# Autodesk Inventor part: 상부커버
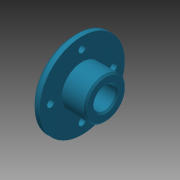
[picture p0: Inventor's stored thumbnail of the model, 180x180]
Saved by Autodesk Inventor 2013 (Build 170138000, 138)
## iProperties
Created: 2015-09
Part Number: 상부커버
Material: 알루미늄 6061
Document SubType Name: Modeling
Designer: mduedu
Density: 1 g/cm^3
Author: mduedu
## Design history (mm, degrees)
sketch "스케치1"
  geometry: L1 (-10, 0)-(10, 0); L2 (-10, 0)-(-10, 27); L3 (-10, 27)-(-5, 27); L4 (-5, 27)-(-5, 13); L5 (-5, 13)-(10, 13); L6 (10, 13)-(10, 0); 2 further points
  constraints: 12 end point, 2 parallel, 2 perpendicular, 1 coincident, 1 horizontal, 1 midpoint, 1 vertical
  dimensions: "d0" = 20 distance of L1.start L1.end; "d2" = 5 distance of L2.end L3.end; "d3" = 26 diameter of L5 L1; "d4" = 54 diameter of L3 L1
revolve "회전1" sketch "스케치1" stored, may be unused: angle "d5" = 90 deg
hole "구멍1" diameter "d8" = 14; stored, may be unused: countersink angle "d12" = 90 deg, drill point angle "d14" = 118 deg; dims "d6" = 10, "d7" = 10, "d9" = 6, "d10" = 4, "d11" = 2, "d13" = 8
chamfer "모따기1" distance "d15" = 1; stored, may be unused: second distance "d16" = 2, angle "d17" = 45 deg
chamfer "모따기2" distance "d18" = 2; stored, may be unused: second distance "d19" = 2, angle "d20" = 45 deg
sketch "스케치2" dims "d21" = 40
  geometry: 6 further points
  constraints: 2 vertical alignment, 1 coincident, 7 other
  dimensions: "d25" = 360 deg dimension on point (0, 0) point (0, 20) (derived)
sketch "스케치3"
  geometry: 4 further points
hole "구멍2" sketch "스케치3" at (0, 20), (-20, 0), (20, 0), (0, -20) diameter "d27" = 4.5; stored, may be unused: countersink angle "d31" = 90 deg, drill point angle "d33" = 0 deg; dims "d28" = 6, "d29" = 4, "d30" = 2, "d32" = 8
node "솔리드1"
